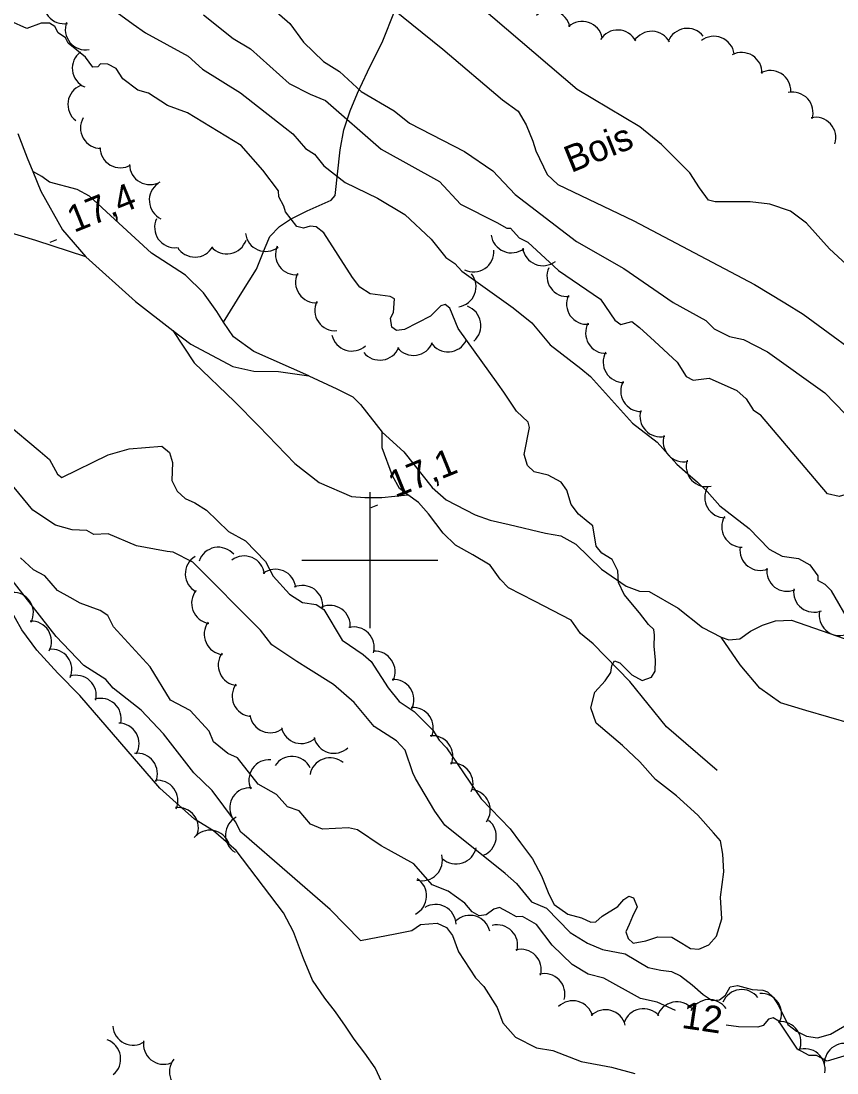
# Model space of a CAD drawing. Extents: x 362852 to 366875, y 5563573 to 5566479.
# Drawn here: x 363948.7 to 364068.7, y 5565324.6 to 5565479.3 of the extents above; entities that cross this region are included whole.
import ezdxf

# ---------------------------------------------------------------- set-up
doc = ezdxf.new("R2010")
doc.units = 0
for name, color, linetype in [('Niveau 1', 7, 'Continuous'), ('Niveau 2', 7, 'Continuous'), ('Niveau 22', 7, 'Continuous'), ('Niveau 3', 7, 'Continuous'), ('Niveau 44', 7, 'Continuous'), ('Niveau 61', 7, 'Continuous')]:
    doc.layers.add(name, color=color, linetype=linetype)

msp = doc.modelspace()

# ---------------------------------------------------------------- linework, layer by layer
at = {"layer": 'Niveau 1'}
msp.add_line((363998.65, 5565344.05), (364003.75, 5565345.04), dxfattribs=at)
for points in [[(363985.18, 5565481.63), (363988.24, 5565478.98), (363990.27, 5565476.21), (363993.21, 5565473.35), (363995.55, 5565471.92), (363998.71, 5565468.94), (364003.58, 5565466.13), (364005.84, 5565464.32), (364013.92, 5565460.11), (364018.1, 5565457.26), (364021.38, 5565453.79), (364030.41, 5565446.89), (364037.36, 5565442.89), (364044.61, 5565437.93), (364049.43, 5565435.27), (364050.66, 5565434.04), (364052.93, 5565432.93), (364055, 5565432.47), (364058.5, 5565430.66), (364066.94, 5565424.63)], [(364071.46, 5565419.94), (364066.94, 5565424.63)], [(363998.65, 5565344.05), (363994.18, 5565348.58), (363981.51, 5565359.57), (363981.03, 5565359.96), (363980.24, 5565361.48), (363976.8, 5565366.13), (363974.1, 5565368.72), (363969.63, 5565374.47), (363966.36, 5565377.94), (363962.25, 5565381.16), (363961.17, 5565382.44), (363957.93, 5565384.51), (363953.87, 5565388.79), (363942.22, 5565403.59)], [(364003.75, 5565345.04), (364006.17, 5565345.52), (364007.46, 5565346.42), (364009.89, 5565346.59), (364011.31, 5565345.94), (364012.17, 5565344.79), (364013.03, 5565342.38), (364015.57, 5565338.54), (364016.79, 5565337.3), (364018.76, 5565334.17), (364019.57, 5565331.94), (364021.42, 5565329.82), (364024.51, 5565328.25), (364026.93, 5565327.88), (364031.08, 5565326.26), (364035.54, 5565325.43), (364038.97, 5565324.48)]]:
    msp.add_lwpolyline(points, dxfattribs=at)
at = {"layer": 'Niveau 2'}
for p, q in [((364044.96, 5565333.76), (364042.3, 5565334.96)), ((364054.24, 5565331.36), (364052.41, 5565331.58))]:
    msp.add_line(p, q, dxfattribs=at)
for points in [[(363957.42, 5565484.54), (363965.21, 5565478.85), (363966.98, 5565477.61), (363973.27, 5565474.14), (363975.39, 5565472.26), (363980.96, 5565468.77), (363987.56, 5565463.61), (363988.7, 5565462.71), (363990.54, 5565460.59), (363991.85, 5565459.73), (363993.22, 5565458.02), (363996.39, 5565455.59), (364001.12, 5565453.25), (364005.16, 5565450.88), (364009.02, 5565447.24), (364011.2, 5565444.52), (364012.51, 5565443.67), (364013.54, 5565442.54), (364021.09, 5565437.14), (364023.84, 5565434.94), (364026.52, 5565431.66), (364031.06, 5565428.21), (364032.46, 5565427.01), (364038.65, 5565420.16), (364042.28, 5565417.34), (364045.16, 5565414.11), (364046.79, 5565412.69)], [(364090.56, 5565424.67), (364067.63, 5565445.8), (364064.23, 5565449.56), (364061.88, 5565451.36), (364058.84, 5565452.37), (364055.96, 5565452.7), (364050.82, 5565452.73), (364049.85, 5565452.96), (364048.49, 5565454.79), (364047.1, 5565456.98), (364045.22, 5565458.85), (364042.9, 5565461.17), (364039.73, 5565463.76), (364030.49, 5565469.27), (364011.72, 5565485.34)], [(364000.34, 5565483.61), (364010.74, 5565475.2), (364019.51, 5565467.74), (364021.82, 5565466.06), (364023.01, 5565464.03), (364023.97, 5565461.67), (364024.43, 5565460.22), (364026.08, 5565456.76), (364027.68, 5565455.28), (364038.83, 5565449.94), (364056.62, 5565440.55), (364061.07, 5565437.86), (364063.74, 5565436.2), (364074.59, 5565428.23)], [(364026.25, 5565412.52), (364024.17, 5565412.99), (364023.19, 5565413.94), (364022.72, 5565415.55), (364023.52, 5565419.5), (364023.29, 5565420.31), (364021.59, 5565421.94), (364019.73, 5565424.74), (364018.87, 5565425.92), (364012.98, 5565434.08), (364011.76, 5565437.1), (364011.08, 5565437.61), (364010.43, 5565437.41), (364008.92, 5565435.92), (364005.11, 5565433.94), (364003.92, 5565433.77), (364003.24, 5565434.28), (364003.05, 5565435.62), (364003.49, 5565436.46), (364003.63, 5565438.45), (364003, 5565438.79), (364000.08, 5565439.17), (363998.56, 5565440.16), (363997.45, 5565441.59), (363993.26, 5565448.16), (363992.12, 5565449.06), (363991.21, 5565449.15), (363990.23, 5565448.86), (363989.28, 5565449.11), (363987.6, 5565451.26), (363987.36, 5565452.1), (363986.62, 5565453.47), (363986.56, 5565454.33), (363984.25, 5565457.36), (363981.1, 5565461.03), (363973.2, 5565465.82), (363970.24, 5565466.9), (363967.45, 5565468.73), (363965.89, 5565469.16), (363963.67, 5565470.82), (363962.69, 5565472.32), (363961.45, 5565473), (363960.38, 5565473.04), (363959.99, 5565472.58), (363959.28, 5565472.55), (363958.17, 5565474), (363955.65, 5565476.09), (363955.23, 5565476.85), (363954.15, 5565477.6), (363953.68, 5565478.51), (363952.87, 5565478.99), (363951.64, 5565478.99), (363949.56, 5565478.21), (363947.14, 5565479.28)], [(363975.54, 5565480.25), (363979.89, 5565476.73), (363982.46, 5565475.21), (363988.14, 5565470.14), (363991.24, 5565468.56), (363993.47, 5565467.62), (364001.68, 5565460.46), (364010.26, 5565455.71), (364013.33, 5565452.36), (364018.7, 5565449.68), (364020.16, 5565448.87), (364020.69, 5565448.85), (364021.97, 5565447.45), (364023.23, 5565446.77), (364027.77, 5565442.6), (364033.92, 5565438.38), (364036.05, 5565435.29), (364036.92, 5565434.67), (364038.57, 5565435.14), (364039.7, 5565434.24), (364041.88, 5565432.21), (364045.22, 5565429.12), (364046.53, 5565427.03), (364047.58, 5565426.46), (364049.94, 5565426.79), (364053.99, 5565424.95)], [(364053.99, 5565424.95), (364055.39, 5565423.76), (364056.41, 5565422.11), (364057.49, 5565421.38)], [(364083.46, 5565388.67), (364081.89, 5565390.51), (364081.38, 5565392.29), (364081.59, 5565393.94), (364081.67, 5565396.78), (364080.37, 5565400.65), (364076.27, 5565406.86), (364074.77, 5565407.85), (364074.15, 5565408.72), (364072.92, 5565409.42), (364070.36, 5565409.75), (364069.04, 5565409.37), (364067.34, 5565409.76), (364057.49, 5565421.38)], [(363946.37, 5565420.32), (363951.49, 5565415.98), (363952.9, 5565414.81), (363954.04, 5565412.65), (363954.71, 5565412.15), (363961.5, 5565415.51), (363964.58, 5565416.39), (363969.4, 5565416.75), (363970.55, 5565415.85), (363970.96, 5565414.37), (363970.87, 5565411.7), (363971.66, 5565410.17), (363972.84, 5565409.09), (363974.27, 5565408.44), (363975.99, 5565407.36), (363979.2, 5565404.22), (363979.2, 5565404.22), (363981.71, 5565402.83), (363984.67, 5565399.82), (363985.81, 5565397.67), (363988.17, 5565395), (363990.1, 5565393.79), (363992.13, 5565393.49), (363993.22, 5565392.76), (363995.94, 5565388.25), (363999.02, 5565386.13), (364000.2, 5565385.07), (364002.72, 5565381.21), (364004.34, 5565379.21), (364006.55, 5565377.73), (364009.26, 5565374.99), (364010.23, 5565373.51), (364011.27, 5565372.39), (364016.4, 5565364.89)], [(364046.79, 5565412.69), (364048.21, 5565411.47), (364049.64, 5565410.1), (364051.49, 5565408), (364055.8, 5565404.67), (364058.78, 5565401.64), (364060.67, 5565400.6), (364063.07, 5565400.23), (364064.73, 5565399.31), (364065.91, 5565397.7), (364065.93, 5565397)], [(364019.93, 5565353.91), (364011.02, 5565361.03), (364009.55, 5565363.06), (364006.74, 5565367.9), (364006.35, 5565368.69), (364005.19, 5565372.05), (364003.91, 5565373.44), (364000.66, 5565375.51), (363997.71, 5565379.07), (363994.67, 5565381.7), (363990.99, 5565384), (363989.27, 5565385.1), (363985.57, 5565387.54), (363983.91, 5565389.71), (363973.96, 5565399.72), (363971.08, 5565401.18), (363970.17, 5565401.28), (363968.32, 5565401.62), (363965.7, 5565402.1), (363961.51, 5565403.87), (363959.41, 5565403.8), (363958.36, 5565404.39), (363956.24, 5565404.48), (363953.74, 5565405.16), (363950.45, 5565407.38), (363947, 5565411.51)], [(364016.4, 5565364.89), (364020.67, 5565360.47), (364022.15, 5565358.42), (364023.92, 5565356.05), (364025.24, 5565353.55), (364026.33, 5565350.88), (364027.13, 5565349.34), (364029.14, 5565347.92), (364031.15, 5565347.38), (364032.52, 5565346.76), (364033.24, 5565346.8), (364034.21, 5565347.64), (364036.48, 5565349.07), (364037.38, 5565350.06), (364038.11, 5565350.55), (364038.81, 5565350.34), (364039.36, 5565349), (364038.63, 5565347.58), (364038.18, 5565346.4), (364037.69, 5565345.33), (364038.02, 5565344.34), (364038.74, 5565343.64), (364040.59, 5565343.97), (364042.39, 5565344.58), (364044.45, 5565344.55), (364045.92, 5565343.66), (364047.17, 5565342.87), (364048.4, 5565342.75), (364049.86, 5565343.41), (364051.02, 5565344.7), (364051.78, 5565347.25), (364051.61, 5565350.42), (364052.08, 5565354.16), (364051.96, 5565356.73), (364051.6, 5565358.7), (364050.56, 5565359.89), (364048.26, 5565362.5), (364045.13, 5565365.33), (364042.05, 5565367.74), (364039.75, 5565370.34), (364037.18, 5565372.72), (364033.29, 5565376.04), (364032.51, 5565378.27), (364033.12, 5565380.58), (364034.61, 5565382.25), (364035.48, 5565383.48), (364035.63, 5565384.48), (364036.02, 5565385.2), (364036.77, 5565384.89), (364038.54, 5565383.12), (364040.05, 5565382.31), (364041.47, 5565382.77), (364041.98, 5565383.66), (364042.05, 5565385.31), (364041.85, 5565387.34), (364041.87, 5565388.97), (364041.78, 5565389.81), (364040.99, 5565390.54), (364039.67, 5565392.25), (364037.41, 5565394.93), (364036.57, 5565396.71), (364036.49, 5565398.42), (364035.64, 5565400.08), (364034.14, 5565401.04), (364033.32, 5565402.04), (364032.81, 5565405.07), (364032.11, 5565405.58), (364030.72, 5565406.77), (364029.61, 5565408.2), (364029, 5565410.32), (364028.14, 5565411.48), (364026.25, 5565412.52)], [(364042.3, 5565334.96), (364039.84, 5565335.5), (364034.41, 5565338.5), (364032.14, 5565339.08), (364029.78, 5565340.53), (364026.85, 5565343.38), (364024.55, 5565346.42), (364022.46, 5565347.59), (364021.59, 5565347.51), (364020.35, 5565348.21), (364019.09, 5565348.9), (364018.27, 5565348.66), (364017.1, 5565347.8), (364016.09, 5565347.68), (364015.04, 5565348.27), (364013.97, 5565349.55), (364011.52, 5565351.31), (364009.16, 5565352.21), (364006.49, 5565355.3), (364002.74, 5565357.4), (364001.67, 5565357.98), (363998.18, 5565360.33), (363996.85, 5565360.64), (363993.05, 5565360.44), (363991.27, 5565361.16), (363989.62, 5565363.14), (363987.89, 5565363.69), (363986.3, 5565365.53), (363983.58, 5565367.05), (363980.52, 5565370.93), (363979.11, 5565371.56), (363977.02, 5565373.26), (363976.38, 5565374.83), (363973.59, 5565377.9), (363970.7, 5565379.38), (363967.68, 5565384.32), (363962.28, 5565390.18), (363961.44, 5565391.86), (363960.35, 5565392.61), (363957.4, 5565393.69), (363955.94, 5565394.5), (363954.05, 5565395.56), (363952.21, 5565397.68), (363950.54, 5565398.59), (363948.62, 5565400.33)], [(364070.82, 5565390.47), (364067.95, 5565395.47), (364066.98, 5565396.43), (364065.93, 5565397)], [(364001.83, 5565318.59), (364002.17, 5565320.98), (364001.77, 5565323.2), (364000.79, 5565325.31), (363999.29, 5565327.45), (363997.69, 5565329.55), (363996.44, 5565331.42), (363994.94, 5565333.56), (363993.39, 5565335.55), (363991.57, 5565338.19), (363990.26, 5565341.41), (363988.79, 5565345.33), (363987.3, 5565348.1), (363980.33, 5565357.27), (363977.03, 5565360.18), (363974.2, 5565361.91), (363971.05, 5565364.75), (363969.11, 5565366.46), (363957.35, 5565380.07), (363954.13, 5565383.39), (363951.01, 5565386.76), (363948.8, 5565389.74), (363946.02, 5565394.74)], [(364019.93, 5565353.91), (364021.59, 5565352.44), (364023.77, 5565349.73), (364025.98, 5565348.78), (364029.47, 5565345.21), (364032.05, 5565343.65), (364034.26, 5565342.7), (364037.59, 5565342.08), (364040.98, 5565340.07), (364042.83, 5565339.67), (364044.39, 5565339.5), (364045.71, 5565338.86), (364047.43, 5565337.51), (364049.05, 5565336.12), (364050.35, 5565335.21), (364051.44, 5565335.29), (364052.32, 5565336.02), (364053, 5565337.24), (364054.1, 5565337.44), (364056.27, 5565336.83), (364057.81, 5565336.72), (364058.51, 5565336.51), (364059.33, 5565335.72), (364060.14, 5565334.49), (364061.52, 5565331.69), (364062.79, 5565330.72), (364064.27, 5565329.95), (364065.85, 5565329.73), (364067.8, 5565330.28), (364071.07, 5565332.18)], [(364070.73, 5565327.3), (364067.31, 5565326.31), (364065.7, 5565327.1), (364064.63, 5565327.12), (364062.93, 5565328.06), (364060.17, 5565332.19), (364059.33, 5565332.66), (364058.67, 5565332.47), (364057.88, 5565331.53), (364057.08, 5565331.3), (364054.24, 5565331.36)]]:
    msp.add_lwpolyline(points, dxfattribs=at)
at = {"layer": 'Niveau 22'}
for points in [[(363978.5, 5565435.03), (363981.19, 5565439.37), (363983.32, 5565442.84), (363984.62, 5565445.99), (363985.28, 5565447.61), (363986.73, 5565449.08), (363988.36, 5565450.18), (363990.79, 5565451.4), (363994.3, 5565452.95), (363994.9, 5565453.66), (363995.65, 5565460.37), (363996.2, 5565463.33), (363997.09, 5565466.12), (363998.21, 5565468.69), (363999.67, 5565471.85), (364001.91, 5565476.42), (364003.62, 5565480.73)], [(363948.2, 5565462.8), (363949.59, 5565459.19), (363950.43, 5565457.17), (363951.62, 5565454.29), (363954.77, 5565448.6), (363958.25, 5565444.61), (363965.51, 5565438.05), (363971.02, 5565433.81), (363973.65, 5565431.79), (363979.87, 5565428.48), (363982.96, 5565427.82), (363986.57, 5565427.74), (363991.03, 5565427.14), (363995.17, 5565425.23), (363997.52, 5565424.01), (363998.65, 5565422.92), (364001.84, 5565418.81), (364005.01, 5565415.95), (364009.16, 5565410.69), (364011.25, 5565408.86), (364015.5, 5565406.68), (364017.7, 5565405.89), (364020.53, 5565405.24), (364025.87, 5565403.98), (364028.12, 5565403.59), (364030.29, 5565402.36), (364034.1, 5565398.68), (364037.7, 5565396.19), (364039.7, 5565395.44), (364041.09, 5565395.39), (364045.39, 5565392.92), (364048.96, 5565390.09), (364051.69, 5565388.65), (364052.83, 5565388.3), (364054.42, 5565388.45), (364056.03, 5565389.54), (364057.77, 5565390.44), (364059.71, 5565391.09), (364062.02, 5565391.16), (364069.78, 5565388.46)], [(363958.25, 5565444.61), (363950.85, 5565447.04), (363946.65, 5565448.29), (363943.31, 5565448.36), (363939.63, 5565447.66), (363936.91, 5565447.79), (363934.99, 5565448.87), (363931.06, 5565451.14), (363926.03, 5565454.77), (363919.98, 5565458.14), (363913.67, 5565460.63), (363910.26, 5565460.83), (363907.34, 5565459.94), (363904.14, 5565459.11), (363900.43, 5565459.06), (363894.51, 5565458.09)], [(363991.03, 5565427.14), (363982.92, 5565430.68), (363979.93, 5565432.87), (363978.5, 5565435.03), (363977.49, 5565436.57), (363975.53, 5565439.33), (363972.91, 5565441.95), (363967.91, 5565445.19), (363963.09, 5565449.58), (363958.76, 5565453.54), (363956.93, 5565454.53), (363952.86, 5565455.61), (363951.74, 5565456.47), (363950.43, 5565457.17)], [(363971.02, 5565433.81), (363974.16, 5565429.03), (363980.1, 5565423.36), (363983.7, 5565419.73), (363988.98, 5565414.24), (363992.57, 5565411.42), (363997.3, 5565409.38), (363999.29, 5565409.2), (364001.76, 5565409.22), (364005.58, 5565409.59)], [(364051.13, 5565369.06), (364043.64, 5565375.46), (364038.27, 5565382.17), (364032.84, 5565387.68), (364030.98, 5565389.23), (364029.65, 5565391.19), (364024.25, 5565393.98), (364020.42, 5565395.92), (364019.18, 5565397.23), (364017.7, 5565399.26), (364015.16, 5565400.78), (364012.59, 5565402.2), (364010.82, 5565403.97), (364008.65, 5565406.81), (364007.15, 5565408.49), (364005.58, 5565409.59), (364004.39, 5565410.53), (364003.33, 5565412.4), (364001.83, 5565416.51), (364001.84, 5565418.81)], [(364102, 5565342.5), (364098.58, 5565344.33), (364093.21, 5565346.34), (364090.43, 5565348.02), (364088.15, 5565351.4), (364086.25, 5565357.16), (364080.96, 5565367.78), (364078.21, 5565370.58), (364073.8, 5565374.03), (364070.94, 5565375.93), (364064.16, 5565377.9), (364060.41, 5565379.01), (364057.36, 5565381.16), (364054.49, 5565384.6), (364051.69, 5565388.65)]]:
    msp.add_lwpolyline(points, dxfattribs=at)
at = {"layer": 'Niveau 3'}
for p, q in [((363952.98, 5565446.78), (363953.94, 5565447.17)), ((364000.22, 5565407.77), (364001.18, 5565408.16))]:
    msp.add_line(p, q, dxfattribs=at)
at = {"layer": 'Niveau 44'}
for centre, start, end in [((363955.01, 5565481.93), 159.5966, 279.5745), ((364026.5, 5565477.88), 11.4197, 131.3976), ((364031.24, 5565476.28), 11.4197, 131.3976), ((363958.2, 5565478.08), 159.5966, 279.5745), ((364036.47, 5565475), 27.8404, 147.8183), ((364041.46, 5565474.81), 27.8404, 147.8183), ((364046.71, 5565475.24), 38.6292, 158.6071), ((364050.63, 5565474.08), 8.0661, 128.044), ((363959.24, 5565472.38), 126.8733, 246.8513), ((364054.71, 5565471.7), 357.8974, 117.8754), ((364058.94, 5565469.04), 357.8974, 117.8754), ((363958.59, 5565467.05), 112.0517, 232.0297), ((364062.21, 5565465.86), 342.2156, 102.1936), ((363960.44, 5565463.58), 149.9662, 269.9442), ((364065.57, 5565462.16), 342.2156, 102.1936), ((363963.31, 5565460.74), 180.252, 300.23), ((363967.65, 5565458.25), 180.252, 300.23), ((363970.56, 5565452.95), 124.7643, 244.7422), ((363971.35, 5565448.97), 154.9523, 274.9302), ((363978.97, 5565448.07), 220.7776, 340.7556), ((363984.69, 5565448.43), 187.2853, 307.2633), ((364020.84, 5565448.22), 187.7723, 307.7503), ((363974.28, 5565447.59), 210.7252, 330.7031), ((363989.13, 5565444.99), 156.6602, 276.6382), ((364015.27, 5565445.4), 243.7405, 3.7185), ((364025.47, 5565446.33), 187.7723, 307.7503), ((363992.08, 5565440.88), 154.5325, 274.5104), ((364012.63, 5565440.25), 278.6809, 38.6588), ((364029.06, 5565441.78), 155.3168, 275.2948), ((364031.95, 5565437.7), 155.3168, 275.2948), ((363994.91, 5565436.76), 154.5325, 274.5104), ((364013.35, 5565434.53), 310.3945, 70.3725), ((364034.75, 5565433.42), 151.1376, 271.1155), ((363997.36, 5565433.77), 192.55, 312.528), ((364001.48, 5565432.43), 218.1409, 338.1189), ((364006.43, 5565433.13), 218.1409, 338.1189), ((364011.51, 5565433.66), 213.8144, 333.7924), ((364037.33, 5565429.14), 151.1376, 271.1155), ((364039.92, 5565424.86), 151.1376, 271.1155), ((364042.75, 5565421.15), 162.8346, 282.8125), ((364046.15, 5565417.48), 162.8346, 282.8125), ((364049.55, 5565413.82), 162.8346, 282.8125), ((364052.27, 5565409.23), 150.0779, 270.0558), ((364054.77, 5565404.91), 150.0779, 270.0558), ((363977.72, 5565398.9), 41.01, 160.9879), ((364057.45, 5565401.49), 172.1337, 292.1117), ((363975.86, 5565397.99), 121.5619, 241.5399), ((363981.52, 5565397.62), 6.9946, 126.9726), ((364061.4, 5565398.42), 172.1337, 292.1117), ((363986.12, 5565395.66), 6.9946, 126.9726), ((363990.09, 5565393.28), 354.1574, 114.1353), ((364065.34, 5565395.35), 172.1337, 292.1117), ((363947.51, 5565392.27), 332.3641, 92.342), ((363976.79, 5565393.67), 140.9904, 260.9683), ((363994.14, 5565390.35), 354.1574, 114.1353), ((364069.12, 5565391.9), 167.5618, 287.5398), ((363950.18, 5565388.05), 332.3641, 92.342), ((363978.64, 5565389.11), 144.2805, 264.2585), ((363997.65, 5565387.17), 344.5231, 104.5011), ((363953.17, 5565383.9), 336.9115, 96.8894), ((363980.7, 5565384.56), 144.2805, 264.2585), ((364000.72, 5565383.62), 333.8039, 93.7819), ((363956.77, 5565380.07), 347.0914, 107.0693), ((363982.75, 5565380), 144.2805, 264.2585), ((364003.5, 5565379.46), 333.8039, 93.7819), ((363960.43, 5565376.67), 347.0914, 107.0693), ((363985.34, 5565377.61), 188.0487, 308.0267), ((364006.35, 5565375.32), 334.602, 94.58), ((363963.06, 5565373.03), 329.7257, 89.7037), ((363989.92, 5565376.02), 193.4624, 313.4403), ((364009.22, 5565371.17), 336.477, 96.4549), ((363994.72, 5565374.59), 193.4624, 313.4403), ((363965.76, 5565368.6), 336.9963, 96.9742), ((363988.57, 5565368.12), 26.6951, 146.673), ((363994.16, 5565367.92), 49.9065, 169.8845), ((363985.22, 5565367.65), 85.5512, 205.5291), ((364012.19, 5565367.15), 336.4574, 96.4353), ((363968.77, 5565364.61), 336.9963, 96.9742), ((363982.39, 5565363.53), 85.5512, 205.5291), ((364014.73, 5565363.26), 323.78, 83.758), ((363971.78, 5565360.61), 336.9963, 96.9742), ((363981.77, 5565359.56), 117.9044, 237.8823), ((364015.61, 5565359.38), 291.2752, 51.2531), ((363976.48, 5565357.27), 20.2673, 140.2453), ((364012.71, 5565358.31), 228.0506, 348.0286), ((364007.69, 5565355.84), 255.6419, 15.6198), ((364005.36, 5565350.6), 297.3031, 57.2811), ((364009.69, 5565346.35), 1.8853, 121.8632), ((364014.72, 5565344.74), 12.9782, 132.9562), ((364018.75, 5565343.35), 344.1159, 104.0938), ((364022.23, 5565339.76), 344.1159, 104.0938), ((364025.71, 5565336.17), 344.0898, 104.0677), ((364054.72, 5565333.82), 37.2612, 157.2391), ((364049.94, 5565332.35), 33.7326, 153.7106), ((364057.56, 5565333.27), 333.3011, 93.279), ((364029.87, 5565332.18), 14.6246, 134.6026), ((364034.69, 5565330.85), 14.6246, 134.6026), ((364040.26, 5565331.02), 41.4359, 161.4139), ((364045.16, 5565332.01), 41.4359, 161.4139), ((363965.19, 5565331.65), 184.1598, 304.1377), ((364060.44, 5565329.11), 335.3765, 95.3545), ((363960.35, 5565326.61), 309.7994, 69.7773), ((363969.69, 5565328.83), 170.9229, 290.9009), ((364063.98, 5565325.13), 349.3187, 109.2967), ((364069.87, 5565325.91), 61.4208, 181.3987), ((363973.53, 5565324.72), 142.1165, 262.0944)]:
    msp.add_arc(centre, 3, start, end, dxfattribs=at)
at = {"layer": 'Niveau 61'}
for p, q in [((364000, 5565410), (364000, 5565390)), ((363990, 5565400), (364010, 5565400))]:
    msp.add_line(p, q, dxfattribs=at)

# ---------------------------------------------------------------- texts
at = {"layer": 'Niveau 2'}
msp.add_text('12', height=3.93, rotation=351.5703, dxfattribs=at).set_placement((364045.76, 5565331.2))
at = {"layer": 'Niveau 3'}
for s, p in [('17,4 ', (363956.49, 5565448.14)), ('17,1 ', (364003.73, 5565409.13))]:
    msp.add_text(s, height=3.93, rotation=22.09, dxfattribs=at).set_placement(p)
at = {"layer": 'Niveau 44'}
msp.add_text('Bois', height=3.93, rotation=22.09, dxfattribs=at).set_placement((364029.62, 5565456.95))

doc.saveas('drawing.dxf')
